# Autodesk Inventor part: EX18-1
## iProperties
Author: Elise Moss
Revision Number: A
Length Units: 11272
Angle Units: 11279
Time Units: 11290
Mass Units: 11286
Shininess: 3
Angle Display Precision: 2
Document Length Units: 11272
Document Angle Units: 11286
Document Time Units: 11279
Document Mass Units: 11290
Document Length Units Precision: 3
Document Angle Units Precision: 0
Compacted: False
PropertySet Name: _Private Model Information
Created: 2001-09
Part Number: EX18-1
Description: BASE, DRILL VISE
Document SubType Name: Modeling
Designer: Elise Moss
Control State: 0
Master: False
Checked Out: False
PropertySet Name: Design Tracking Control
Density: 0.0
Volumn: 0.0
Area: 0.0
PropertySet Name: Model Information
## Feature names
1. Extrusion1
2. Extrusion5
3. Extrusion3
4. Extrusion4
5. Hole1
6. Fillet1
7. Hole2
